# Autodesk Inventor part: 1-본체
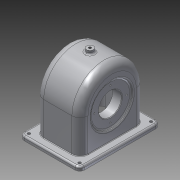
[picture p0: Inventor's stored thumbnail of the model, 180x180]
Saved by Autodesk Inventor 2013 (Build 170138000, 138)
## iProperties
Created: 2016-01
Part Number: 1-본체
Material: 알루미늄 6061
Document SubType Name: Modeling
Designer: Administrator
Density: 2.71 g/cm^3
Mass: 754.265 g
Surface Area: 999.521 cm^2
Volume: 278.327 cm^3
Author: Administrator
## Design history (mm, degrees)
sketch "스케치1"
  geometry: L1 (-52, 70)-(52, 70); L2 (52, 70)-(52, -70); L3 (52, -70)-(-52, -70); L4 (-52, -70)-(-52, 70); 3 further points
  constraints: 8 end point, 2 midpoint, 2 parallel, 1 horizontal, 1 horizontal alignment, 1 perpendicular, 1 vertical alignment
  dimensions: "d0" = 104 distance between parallel lines of L2 L4; "d2" = 140 distance between parallel lines of L3 L1
extrude "돌출1" new body sketch "스케치1" distance "d3" = 7; taper "d4" = 0 deg
sketch "스케치3"
  geometry: L1 (-38.5, 56)-(38.5, 56); L2 (38.5, 56)-(38.5, -56); L3 (38.5, -56)-(-38.5, -56); L4 (-38.5, -56)-(-38.5, 56); 3 further points
  constraints: 8 end point, 2 midpoint, 2 parallel, 1 horizontal, 1 horizontal alignment, 1 perpendicular, 1 vertical alignment
  dimensions: "d5" = 77 distance between parallel lines of L2 L4; "d7" = 112 distance between parallel lines of L1 L3
extrude "돌출2" join sketch "스케치3" distance "d8" = 114; taper "d9" = 0 deg
fillet "모깎기1" dims "d10" = 56
feature "쉘1" dims "d11" = 7, "d12" = 5
sketch "스케치19"
  geometry: L1 (-38.5, 7)-(-38.5, 65) reference; L2 (-33.5, 0)-(-33.5, 65) reference; L3 (-38.5, 65)-(-38.5, 121) reference; L4 (-33.5, 65)-(-33.5, 116) reference; L5 (-38.5, 60)-(-19.5, 60); L6 (-19.5, 60)-(-19.5, 88); L7 (-19.5, 88)-(-38.5, 103.943); L8 (-52, 0)-(52, 0) reference; L9 (-38.5, 97.416)-(-35.5, 94.899); L10 (-35.5, 94.899)-(-35.5, 60); 1 further point
  constraints: 10 end point, 4 point on line, 3 perpendicular, 1 parallel
  dimensions: "d108" = 56 diameter of L6.end L5; "d111" = 50 deg angle of L7 L6; "d113" = 3 distance between parallel lines of L3 L10; "d114" = 5 distance between parallel lines of L7 L9; "d115" = 16 distance between parallel lines of L10 L6; "d116" = 60 distance from line of L8 L5.start
revolve "회전3" sketch "스케치19" stored, may be unused: angle "d117" = 90 deg
sketch "스케치20"
  geometry: L1 (-38.5, 65)-(-38.5, 121) reference; L2 (-38.5, 7)-(-38.5, 65) reference; L3 (-19.5, 32)-(-19.5, 88) reference; L4 (-33.5, 99.747)-(-19.5, 88) reference; L5 (-38.5, 60)-(-19.5, 60); L6 (-52, 0)-(52, 0) reference; L7 (-38.5, 97.416)-(-35.5, 94.899); L8 (-35.5, 94.899)-(-35.5, 60); 1 further point
  constraints: 6 end point, 3 point on line, 2 perpendicular, 1 midpoint, 1 parallel
  dimensions: "d118" = 60 distance between parallel lines of L6 L5; "d119" = 3 distance between parallel lines of L1 L8; "d120" = 5 distance between parallel lines of L4 L7
revolve "회전4" sketch "스케치20" stored, may be unused: angle "d121" = 90 deg
node "작업 평면1"
sketch "스케치10"
  geometry: C1 r 6 at (0, 0); 1 further point
  constraints: 1 centre point, 1 coincident
  dimensions: "d32" = 12 diameter of C1
extrude "돌출4" join sketch "스케치10" stored distance "d34" = 10; taper "d35" = 0 deg
sketch "스케치14"
  geometry: 2 further points
  constraints: 1 coincident
hole "구멍2" sketch "스케치14" at (0, 0) diameter "d55" = 4.459; stored, may be unused: countersink angle "d59" = 90 deg, drill point angle "d61" = 118 deg; dims "d56" = 7, "d57" = 4, "d58" = 2, "d60" = 9
sketch "스케치16"
  geometry: L1 (52, 70)-(52, -70) reference; L2 (52, -70)-(-52, -70) reference; C1 r 2.5 at (44, -62); 1 further point
  constraints: 1 centre point
  dimensions: "d73" = 8 distance from line of L1 C1.centre; "d74" = 8 distance from line of L2 C1.centre; "d76" = 5 diameter of C1
extrude "돌출7" cut sketch "스케치16" distance "d77" = 16; taper "d78" = 0 deg
fillet "모깎기2" dims "d85" = 14
fillet "모깎기3" dims "d86" = 8
fillet "모깎기4" dims "d87" = 9
fillet "모깎기5" dims "d88" = 3
sketch "스케치17"
  geometry: L1 (-19.5, 65)-(68.5, 65) reference; L2 (63, 0)-(63, 58) reference; 3 further points
  constraints: 1 other
  dimensions: "d92" = 30 distance from line of point (24.5, 35) L1; "d93" = 38.5 distance from line of L2 point (24.5, 35)
feature "엠보싱1" sketch "스케치17" dims "d0" = 104, "d2" = 140, "d11" = 7, "d94" = 0.5, "d95" = 0
sketch "스케치21"
  geometry: C1 r 34.899 at (0, 0) reference; C2 r 20 at (0, 0); 1 further point
  constraints: 1 centre point, 1 coincident
  dimensions: "d122" = 40 diameter of C2
extrude "돌출8" cut sketch "스케치21" distance "d124" = 16; taper "d125" = 0 deg
sketch "스케치22"
  geometry: C1 r 20 at (0, 0) reference; C2 r 34.899 at (0, 0) reference; 2 further points
  constraints: 1 horizontal alignment
  dimensions: "d126" = 28 distance of point (-28, 0) C1.centre
hole "구멍4" sketch "스케치22" at (-28, 0) diameter "d127" = 2.459; stored, may be unused: countersink angle "d131" = 90 deg, drill point angle "d133" = 118 deg; dims "d128" = 7, "d129" = 4, "d130" = 2, "d132" = 9
sketch "스케치23"
  geometry: C1 r 20 at (-5, 0) reference; C2 r 31 at (-5, 0); 1 further point
  constraints: 1 centre point, 1 coincident
  dimensions: "d137" = 62 diameter of C2
extrude "돌출9" join sketch "스케치23" distance "d139" = 10; taper "d140" = 0 deg
sketch "스케치24"
  geometry: C1 r 20 at (0, 0) reference; C2 r 20 at (0, 0); 1 further point
  constraints: 1 centre point, 1 coincident
  dimensions: "d141" = 40 diameter of C2
extrude "돌출10" cut sketch "스케치24" distance "d143" = 15; taper "d144" = 0 deg
sketch "스케치25"
  geometry: C1 r 20 at (0, 0) reference; C2 r 31 at (0, 0) reference; 2 further points
  constraints: 1 horizontal alignment
  dimensions: "d145" = 24 distance of C1.centre point (24, 0)
hole "구멍5" sketch "스케치25" at (24, 0) diameter "d146" = 2.459; stored, may be unused: countersink angle "d150" = 90 deg, drill point angle "d152" = 118 deg; dims "d147" = 6, "d148" = 4, "d149" = 2, "d151" = 8
fillet "모깎기7" dims "d156" = 3
chamfer "모따기2" distance "d157" = 1; stored, may be unused: second distance "d158" = 2, angle "d159" = 45 deg
fillet "모깎기8" dims "d160" = 1
node "솔리드1"
pattern_linear "직사각형 패턴1" dims "d81" = 88, "d84" = 124
pattern_circular "원형 패턴3" dims angle "d135" = 360 deg
pattern_circular "원형 패턴4" dims angle "d154" = 360 deg
node "투영된 루프5"
node "투영된 루프6"
node "투영된 루프7"
other parameters: "d31" = 127
